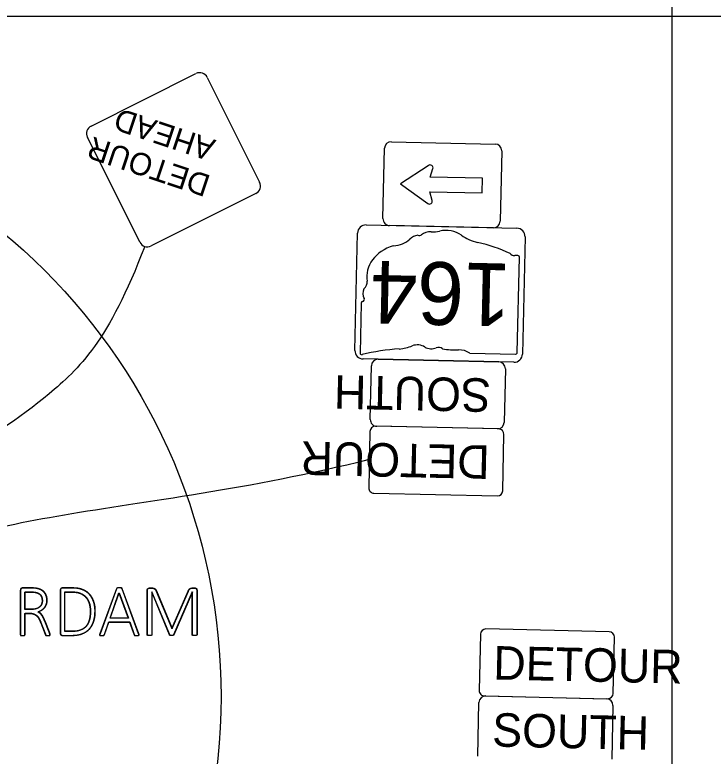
# Model space of a CAD drawing. Extents: x -202 to 1556, y 0 to 676.
# Drawn here: x 251.9 to 356.1, y 109.6 to 220.2 of the extents above; entities that cross this region are included whole.
import ezdxf

# ---------------------------------------------------------------- set-up
doc = ezdxf.new("R2010")
doc.units = 0
for name, color, linetype in [('GM_X_Minor_Lake', 7, 'Continuous'), ('GM_X_Minor_Lake_Text', 7, 'Continuous'), ('GM_X_Minor_River_Text', 7, 'Continuous'), ('GM_X_Unincorporated', 7, 'Continuous'), ('SH_Data', 7, 'Continuous')]:
    doc.layers.add(name, color=color, linetype=linetype)

msp = doc.modelspace()

# ---------------------------------------------------------------- linework, layer by layer
at = {"layer": 'GM_X_Minor_Lake'}
for p, q in [((326.89, 169.82), (327.2, 184.05)), ((303.61, 177.18), (303.45, 169.74)), ((303.61, 177.18), (303.61, 177.18)), ((319.79, 169.73), (326.65, 169.58)), ((306.14, 168.81), (324.14, 168.41)), ((304.95, 159.83), (305.12, 167.83)), ((325.12, 167.39), (324.94, 159.39)), ((323.92, 158.41), (305.92, 158.81)), ((322.19, 118.56), (340.18, 118.16)), ((320.99, 109.58), (321.17, 117.58)), ((341.16, 117.14), (340.99, 109.14))]:
    msp.add_line(p, q, dxfattribs=at)
for points in [[(263.29, 203.61), (278.94, 211.44)], [(280.62, 210.88), (288.44, 195.23)], [(270.55, 186.28), (262.73, 201.94)], [(287.88, 193.55), (272.23, 185.72)], [(304.33, 188.85), (326.83, 188.36)], [(302.67, 170.13), (303.06, 187.63)], [(328.05, 187.08), (327.67, 169.58)], [(326.39, 168.36), (303.89, 168.85)], [(324.12, 158.41), (305.72, 158.81)], [(304.91, 158.03), (304.72, 149.63)], [(324.72, 149.19), (324.9, 157.59)], [(305.5, 148.81), (323.9, 148.41)], [(340.6, 128.15), (322.21, 128.56)], [(321.39, 127.78), (321.21, 119.38)], [(341.2, 118.94), (341.39, 127.34)], [(321.99, 118.56), (340.38, 118.16)]]:
    msp.add_lwpolyline(points, dxfattribs=at)
for centre, radius, start, end in [((279.5, 210.32), 1.25, 26.565, 116.565), ((263.85, 202.49), 1.25, 116.565, 206.565), ((287.32, 194.67), 1.25, 296.565, 26.565), ((304.31, 187.6), 1.25, 88.742, 178.742), ((326.8, 187.11), 1.25, 358.742, 88.742), ((271.67, 186.84), 1.25, 206.565, 296.565), ((303.92, 170.1), 1.25, 178.742, 268.742), ((326.42, 169.61), 1.25, 268.742, 358.742), ((306.12, 167.81), 1, 88.742, 178.742), ((324.12, 167.41), 1, 358.742, 88.742), ((305.95, 159.81), 1, 178.742, 268.742), ((323.94, 159.41), 1, 268.742, 358.742), ((305.71, 158.01), 0.8, 88.742, 178.742), ((324.1, 157.61), 0.8, 358.742, 88.742), ((305.52, 149.61), 0.8, 178.742, 268.742), ((323.92, 149.21), 0.8, 268.742, 358.742), ((322.19, 127.76), 0.8, 88.742, 178.742), ((340.59, 127.35), 0.8, 358.742, 88.742), ((322.17, 117.56), 1, 88.742, 178.742), ((322.01, 119.36), 0.8, 178.742, 268.742), ((340.4, 118.96), 0.8, 268.742, 358.742), ((340.16, 117.16), 1, 358.742, 88.742)]:
    msp.add_arc(centre, radius, start, end, dxfattribs=at)
for centre, major_axis, start_param, end_param in [((316.25, 185.18), (-3.56, 0.08), 4.026481, 4.996735), ((312.45, 185.75), (-2.01, 0.04), 4.937069, 5.64225), ((312.26, 187.71), (-0.534, 0.012), 1.147584, 2.315152), ((313.95, 186.3), (-1.9, 0.04), 4.691044, 5.507374), ((314.29, 190.15), (-2.93, 0.06), 1.495662, 1.94098), ((322.44, 190.55), (-5.61, 0.12), 0.823519, 1.323587), ((308.19, 188.46), (-3.4, 0.07), 1.647645, 2.488434), ((316.69, 172.31), (-17.94, 0.39), 4.195997, 4.488961), ((310.65, 181.09), (-6.22, 0.14), 5.101752, 6.440018), ((326.48, 184.89), (-0.754, 0.017), 0.519207, 1.627899), ((326.86, 182.63), (-2.09, 0.05), 4.665946, 4.897461), ((326.93, 184.09), (-0.274, 0.006), 3.00124, 4.508301), ((302.74, 180.32), (-1.76, 0.04), 2.387724, 3.262537), ((306.27, 178.61), (-2.42, 0.05), 5.934695, 6.695948), ((303.89, 177.2), (-0.279, 0.006), 5.05454, 6.418171), ((303.68, 177.73), (-0.404, 0.009), 1.883978, 3.671073), ((308.73, 174.32), (-5, 0.11), 1.699011, 2.107814), ((311.97, 169.43), (-1.9, 0.04), 4.081561, 5.145723), ((314.06, 171.64), (-1.58, 0.03), 0.950623, 2.079405), ((315.14, 169.98), (-0.76, 0.017), 3.836095, 5.185415), ((303.7, 169.7), (-0.261, 0.006), 6.141152, 7.989035), ((311.37, 150.51), (-24.85, 0.55), 4.814394, 5.042369), ((317.46, 177.78), (-9.45, 0.21), 1.404758, 1.657858), ((318.12, 168.12), (-2.63, 0.06), 4.042523, 4.731795), ((326.62, 169.8), (-0.271, 0.006), 1.712693, 3.28349)]:
    msp.add_ellipse(centre, major_axis=major_axis, ratio=0.8, start_param=start_param, end_param=end_param, dxfattribs=at)
at = {"layer": 'GM_X_Minor_Lake_Text'}
for p, q in [((306.85, 189.79), (307.08, 200.29)), ((308.11, 201.27), (323.6, 200.93)), ((324.58, 199.91), (324.35, 189.41)), ((313.61, 197.69), (309.47, 194.99)), ((313.87, 195.99), (314.29, 197.26)), ((321.68, 195.81), (313.87, 195.99)), ((321.63, 193.63), (321.68, 195.81)), ((309.47, 194.99), (313.54, 192.05)), ((313.82, 193.8), (321.63, 193.63)), ((314.19, 192.51), (313.82, 193.8)), ((323.33, 188.43), (307.83, 188.77))]:
    msp.add_line(p, q, dxfattribs=at)
for centre, radius, start, end in [((308.08, 200.27), 1, 88.742, 178.742), ((323.58, 199.93), 1, 358.742, 88.742), ((313.9, 197.39), 0.417, 341.5374, 133.7516), ((313.79, 192.39), 0.417, 234.1532, 15.9466), ((307.85, 189.77), 1, 178.742, 268.742), ((323.35, 189.43), 1, 268.742, 358.742)]:
    msp.add_arc(centre, radius, start, end, dxfattribs=at)
at = {"layer": 'GM_X_Minor_River_Text'}
for p, q in [((350, 10), (350, 430)), ((30, 220), (640, 220))]:
    msp.add_line(p, q, dxfattribs=at)
at = {"layer": 'GM_X_Unincorporated'}
for p, q in [((252.72, 134.32), (252.72, 127.71)), ((252.76, 134.34), (252.76, 127.72)), ((254.35, 134.67), (253.02, 134.67)), ((254.39, 134.68), (253.06, 134.68)), ((258.67, 134.32), (258.67, 127.94)), ((258.71, 134.34), (258.71, 127.96)), ((260.46, 134.67), (258.98, 134.67)), ((260.5, 134.68), (259.02, 134.68)), ((267.05, 134.55), (264.58, 127.82)), ((267.09, 134.56), (264.62, 127.84)), ((270.38, 127.82), (267.9, 134.55)), ((270.42, 127.84), (267.94, 134.56)), ((271.66, 127.71), (271.66, 134.32)), ((271.7, 127.72), (271.7, 134.34)), ((271.97, 134.67), (272.33, 134.67)), ((272.01, 134.68), (272.37, 134.68)), ((278.35, 134.67), (278.75, 134.67)), ((278.39, 134.68), (278.78, 134.68)), ((279.05, 134.32), (279.05, 127.71)), ((279.09, 134.34), (279.09, 127.72)), ((255.97, 132.77), (255.97, 132.77)), ((256.01, 132.79), (256.01, 132.79)), ((263.15, 131.2), (263.15, 131.2)), ((263.19, 131.22), (263.19, 131.22)), ((263.87, 131.24), (263.87, 131.24)), ((263.91, 131.25), (263.91, 131.25)), ((255.76, 129.49), (256.42, 127.78)), ((255.8, 129.51), (256.46, 127.79)), ((257.03, 128.08), (256.37, 129.73)), ((257.07, 128.1), (256.41, 129.75)), ((257.14, 127.72), (257.14, 127.72)), ((257.18, 127.73), (257.18, 127.73)), ((258.98, 127.6), (260.37, 127.6)), ((259.02, 127.61), (260.41, 127.61))]:
    msp.add_line(p, q, dxfattribs=at)
for points in [[(254.4, 131.48), (253.38, 131.48), (253.38, 134.07), (254.26, 134.07)], [(254.44, 131.5), (253.42, 131.5), (253.42, 134.09), (254.3, 134.09)], [(260.43, 128.19), (259.34, 128.19), (259.34, 134.07), (260.43, 134.07)], [(260.47, 128.21), (259.38, 128.21), (259.38, 134.09), (260.47, 134.09)], [(274.98, 127.67), (272.33, 134.08), (272.33, 134.08), (272.33, 127.71)], [(275.02, 127.69), (272.37, 134.1), (272.37, 134.1), (272.37, 127.72)], [(272.98, 134.22), (275.32, 128.61), (275.35, 128.61), (277.78, 134.2)], [(273.02, 134.24), (275.36, 128.62), (275.39, 128.62), (277.82, 134.22)], [(278.38, 127.71), (278.38, 134.08), (278.37, 134.08), (275.59, 127.67)], [(278.42, 127.72), (278.42, 134.1), (278.41, 134.1), (275.63, 127.69)], [(253.38, 127.71), (253.38, 130.89), (254.12, 130.89)], [(253.42, 127.72), (253.42, 130.91), (254.16, 130.91)], [(265.26, 127.72), (265.91, 129.59), (269.01, 129.59), (269.69, 127.71)], [(265.3, 127.73), (265.95, 129.61), (269.05, 129.61), (269.73, 127.72)]]:
    msp.add_lwpolyline(points, dxfattribs=at)
for points in [[(267.44, 133.95), (268.81, 130.15), (266.11, 130.15), (267.44, 133.95)], [(267.48, 133.97), (268.85, 130.17), (266.15, 130.17), (267.48, 133.97)]]:
    msp.add_lwpolyline(points, close=True, dxfattribs=at)
for points in [[(252.82, 134.59), (252.72, 134.52), (252.72, 134.32)], [(252.86, 134.61), (252.76, 134.54), (252.76, 134.34)], [(253.02, 134.67), (252.92, 134.67), (252.82, 134.59)], [(253.06, 134.68), (252.96, 134.68), (252.86, 134.61)], [(254.26, 134.07), (254.56, 134.07), (254.74, 134.05)], [(254.3, 134.09), (254.6, 134.09), (254.78, 134.07)], [(254.79, 134.65), (254.61, 134.67), (254.35, 134.67)], [(254.83, 134.67), (254.65, 134.68), (254.39, 134.68)], [(254.74, 134.05), (254.93, 134.04), (255.09, 133.99)], [(254.78, 134.07), (254.97, 134.05), (255.13, 134.01)], [(255.1, 134.62), (254.96, 134.64), (254.79, 134.65)], [(255.14, 134.63), (255, 134.66), (254.83, 134.67)], [(255.09, 133.99), (255.57, 133.86), (255.77, 133.54)], [(255.8, 134.39), (255.5, 134.55), (255.1, 134.62)], [(255.13, 134.01), (255.61, 133.87), (255.81, 133.56)], [(255.84, 134.41), (255.54, 134.56), (255.14, 134.63)], [(256.3, 134), (256.11, 134.23), (255.8, 134.39)], [(256.34, 134.01), (256.15, 134.25), (255.84, 134.41)], [(256.59, 133.47), (256.5, 133.77), (256.3, 134)], [(256.63, 133.49), (256.54, 133.78), (256.34, 134.01)], [(258.78, 134.59), (258.67, 134.52), (258.67, 134.32)], [(258.81, 134.61), (258.71, 134.54), (258.71, 134.34)], [(258.98, 134.67), (258.88, 134.67), (258.78, 134.59)], [(259.02, 134.68), (258.92, 134.68), (258.81, 134.61)], [(260.43, 134.07), (261.2, 134.07), (261.69, 133.86)], [(261.98, 134.42), (261.36, 134.67), (260.46, 134.67)], [(260.47, 134.09), (261.24, 134.09), (261.73, 133.87)], [(262.02, 134.44), (261.4, 134.68), (260.5, 134.68)], [(261.73, 133.87), (262.23, 133.66), (262.56, 133.28)], [(263.02, 133.73), (262.6, 134.18), (261.98, 134.42)], [(263.06, 133.74), (262.64, 134.19), (262.02, 134.44)], [(267.1, 134.62), (267.07, 134.59), (267.05, 134.55)], [(267.14, 134.64), (267.11, 134.61), (267.09, 134.56)], [(267.18, 134.67), (267.13, 134.65), (267.1, 134.62)], [(267.22, 134.68), (267.17, 134.67), (267.14, 134.64)], [(267.31, 134.69), (267.24, 134.68), (267.18, 134.67)], [(267.35, 134.71), (267.27, 134.7), (267.22, 134.68)], [(267.48, 134.7), (267.38, 134.7), (267.31, 134.69)], [(267.52, 134.72), (267.42, 134.72), (267.35, 134.71)], [(267.65, 134.69), (267.57, 134.7), (267.48, 134.7)], [(267.69, 134.71), (267.61, 134.72), (267.52, 134.72)], [(267.77, 134.67), (267.72, 134.68), (267.65, 134.69)], [(267.81, 134.68), (267.76, 134.7), (267.69, 134.71)], [(267.86, 134.62), (267.83, 134.65), (267.77, 134.67)], [(267.9, 134.64), (267.87, 134.67), (267.81, 134.68)], [(267.9, 134.55), (267.89, 134.59), (267.86, 134.62)], [(267.94, 134.56), (267.93, 134.61), (267.9, 134.64)], [(271.66, 134.32), (271.66, 134.52), (271.77, 134.59)], [(271.7, 134.34), (271.7, 134.54), (271.81, 134.61)], [(271.77, 134.59), (271.87, 134.67), (271.97, 134.67)], [(271.81, 134.61), (271.91, 134.68), (272.01, 134.68)], [(272.33, 134.67), (272.47, 134.67), (272.57, 134.64)], [(272.37, 134.68), (272.51, 134.68), (272.61, 134.65)], [(272.57, 134.64), (272.67, 134.61), (272.75, 134.55)], [(272.61, 134.65), (272.71, 134.62), (272.79, 134.57)], [(272.75, 134.55), (272.83, 134.49), (272.89, 134.41)], [(272.79, 134.57), (272.87, 134.51), (272.93, 134.43)], [(272.89, 134.41), (272.94, 134.33), (272.98, 134.22)], [(272.93, 134.43), (272.98, 134.34), (273.02, 134.24)], [(277.78, 134.2), (277.83, 134.33), (277.9, 134.42)], [(277.82, 134.22), (277.87, 134.35), (277.93, 134.44)], [(277.9, 134.42), (277.96, 134.51), (278.03, 134.57)], [(277.93, 134.44), (278, 134.53), (278.07, 134.59)], [(278.03, 134.57), (278.09, 134.62), (278.17, 134.65)], [(278.07, 134.59), (278.13, 134.64), (278.21, 134.66)], [(278.17, 134.65), (278.25, 134.67), (278.35, 134.67)], [(278.21, 134.66), (278.29, 134.68), (278.39, 134.68)], [(278.75, 134.67), (278.79, 134.67), (278.85, 134.65)], [(278.78, 134.68), (278.83, 134.68), (278.89, 134.67)], [(278.85, 134.65), (278.9, 134.63), (278.95, 134.59)], [(278.89, 134.67), (278.94, 134.65), (278.99, 134.61)], [(278.95, 134.59), (278.99, 134.55), (279.02, 134.49)], [(278.99, 134.61), (279.03, 134.57), (279.06, 134.5)], [(279.02, 134.49), (279.05, 134.42), (279.05, 134.32)], [(279.06, 134.5), (279.09, 134.44), (279.09, 134.34)], [(255.77, 133.54), (255.97, 133.23), (255.97, 132.77)], [(255.81, 133.56), (256.01, 133.24), (256.01, 132.79)], [(255.97, 132.77), (255.97, 132.5), (255.88, 132.27)], [(256.01, 132.79), (256.01, 132.52), (255.92, 132.28)], [(256.69, 132.84), (256.69, 133.18), (256.59, 133.47)], [(256.59, 132.22), (256.69, 132.49), (256.69, 132.84)], [(256.73, 132.86), (256.73, 133.2), (256.63, 133.49)], [(256.63, 132.23), (256.73, 132.51), (256.73, 132.86)], [(261.69, 133.86), (262.19, 133.64), (262.52, 133.26)], [(262.52, 133.26), (262.84, 132.88), (263, 132.35)], [(262.56, 133.28), (262.88, 132.89), (263.04, 132.37)], [(263.65, 132.64), (263.44, 133.27), (263.02, 133.73)], [(263.69, 132.66), (263.48, 133.29), (263.06, 133.74)], [(255.6, 131.86), (255.4, 131.68), (255.11, 131.58)], [(255.64, 131.87), (255.44, 131.7), (255.15, 131.6)], [(255.88, 132.27), (255.79, 132.03), (255.6, 131.86)], [(255.92, 132.28), (255.83, 132.05), (255.64, 131.87)], [(255.88, 131.37), (256.13, 131.52), (256.31, 131.73)], [(255.92, 131.39), (256.17, 131.54), (256.35, 131.75)], [(256.31, 131.73), (256.49, 131.94), (256.59, 132.22)], [(256.35, 131.75), (256.53, 131.96), (256.63, 132.23)], [(263, 132.35), (263.15, 131.82), (263.15, 131.2)], [(263.04, 132.37), (263.19, 131.84), (263.19, 131.22)], [(263.87, 131.24), (263.87, 132.01), (263.65, 132.64)], [(263.91, 131.25), (263.91, 132.03), (263.69, 132.66)], [(254.12, 130.89), (254.48, 130.89), (254.74, 130.78)], [(254.16, 130.91), (254.52, 130.91), (254.78, 130.8)], [(255.11, 131.58), (254.81, 131.48), (254.4, 131.48)], [(255.15, 131.6), (254.85, 131.5), (254.44, 131.5)], [(254.74, 130.78), (255.01, 130.67), (255.19, 130.49)], [(254.78, 130.8), (255.05, 130.69), (255.23, 130.5)], [(255.33, 131.11), (255.63, 131.22), (255.88, 131.37)], [(255.65, 130.91), (255.51, 131.03), (255.33, 131.11)], [(255.37, 131.13), (255.67, 131.23), (255.92, 131.39)], [(255.69, 130.93), (255.55, 131.05), (255.37, 131.13)], [(255.92, 130.62), (255.8, 130.79), (255.65, 130.91)], [(255.96, 130.64), (255.84, 130.81), (255.69, 130.93)], [(256.15, 130.23), (256.05, 130.45), (255.92, 130.62)], [(256.19, 130.25), (256.09, 130.47), (255.96, 130.64)], [(263.15, 131.2), (263.15, 130.42), (262.99, 129.86)], [(263.19, 131.22), (263.19, 130.44), (263.03, 129.87)], [(263.64, 129.67), (263.87, 130.35), (263.87, 131.24)], [(263.68, 129.68), (263.91, 130.36), (263.91, 131.25)], [(255.19, 130.49), (255.38, 130.3), (255.51, 130.04)], [(255.23, 130.5), (255.42, 130.31), (255.55, 130.06)], [(255.51, 130.04), (255.64, 129.78), (255.76, 129.49)], [(255.55, 130.06), (255.68, 129.8), (255.8, 129.51)], [(256.37, 129.73), (256.26, 130.01), (256.15, 130.23)], [(256.41, 129.75), (256.3, 130.02), (256.19, 130.25)], [(262.99, 129.86), (262.82, 129.29), (262.49, 128.92)], [(263.03, 129.87), (262.86, 129.31), (262.53, 128.94)], [(262.98, 128.53), (263.42, 128.99), (263.64, 129.67)], [(263.02, 128.54), (263.46, 129), (263.68, 129.68)], [(261.65, 128.37), (261.15, 128.19), (260.43, 128.19)], [(261.69, 128.39), (261.19, 128.21), (260.47, 128.21)], [(262.49, 128.92), (262.15, 128.55), (261.65, 128.37)], [(262.53, 128.94), (262.19, 128.56), (261.69, 128.39)], [(261.9, 127.83), (262.54, 128.07), (262.98, 128.53)], [(261.94, 127.85), (262.58, 128.08), (263.02, 128.54)], [(252.72, 127.71), (252.72, 127.67), (252.73, 127.65)], [(252.73, 127.65), (252.75, 127.62), (252.79, 127.6)], [(252.76, 127.72), (252.76, 127.69), (252.77, 127.66)], [(252.77, 127.66), (252.79, 127.64), (252.83, 127.62)], [(252.79, 127.6), (252.83, 127.59), (252.89, 127.58)], [(252.83, 127.62), (252.87, 127.6), (252.93, 127.59)], [(252.89, 127.58), (252.96, 127.57), (253.05, 127.57)], [(252.93, 127.59), (253, 127.58), (253.09, 127.58)], [(253.05, 127.57), (253.15, 127.57), (253.21, 127.58)], [(253.09, 127.58), (253.19, 127.58), (253.25, 127.59)], [(253.21, 127.58), (253.27, 127.59), (253.31, 127.6)], [(253.25, 127.59), (253.31, 127.6), (253.35, 127.62)], [(253.31, 127.6), (253.35, 127.62), (253.37, 127.65)], [(253.35, 127.62), (253.39, 127.64), (253.41, 127.66)], [(253.37, 127.65), (253.38, 127.67), (253.38, 127.71)], [(253.41, 127.66), (253.42, 127.69), (253.42, 127.72)], [(256.42, 127.78), (256.44, 127.71), (256.47, 127.67)], [(256.46, 127.79), (256.48, 127.73), (256.51, 127.69)], [(256.47, 127.67), (256.49, 127.63), (256.54, 127.61)], [(256.51, 127.69), (256.53, 127.65), (256.58, 127.62)], [(256.54, 127.61), (256.58, 127.58), (256.64, 127.57)], [(256.58, 127.62), (256.62, 127.6), (256.68, 127.59)], [(256.64, 127.57), (256.71, 127.57), (256.8, 127.57)], [(256.68, 127.59), (256.75, 127.58), (256.84, 127.58)], [(256.8, 127.57), (256.9, 127.57), (256.97, 127.58)], [(256.84, 127.58), (256.94, 127.58), (257.01, 127.59)], [(256.97, 127.58), (257.04, 127.59), (257.08, 127.61)], [(257.01, 127.59), (257.08, 127.6), (257.12, 127.62)], [(257.12, 127.82), (257.11, 127.89), (257.03, 128.08)], [(257.16, 127.84), (257.15, 127.91), (257.07, 128.1)], [(257.08, 127.61), (257.12, 127.63), (257.13, 127.65)], [(257.14, 127.72), (257.14, 127.75), (257.12, 127.82)], [(257.12, 127.62), (257.16, 127.64), (257.17, 127.67)], [(257.13, 127.65), (257.14, 127.68), (257.14, 127.72)], [(257.18, 127.73), (257.18, 127.77), (257.16, 127.84)], [(257.17, 127.67), (257.18, 127.7), (257.18, 127.73)], [(258.67, 127.94), (258.67, 127.75), (258.78, 127.67)], [(258.71, 127.96), (258.71, 127.76), (258.81, 127.69)], [(258.78, 127.67), (258.88, 127.6), (258.98, 127.6)], [(258.81, 127.69), (258.92, 127.61), (259.02, 127.61)], [(260.37, 127.6), (261.26, 127.6), (261.9, 127.83)], [(260.41, 127.61), (261.3, 127.61), (261.94, 127.85)], [(264.58, 127.82), (264.54, 127.74), (264.55, 127.69)], [(264.55, 127.69), (264.55, 127.64), (264.59, 127.61)], [(264.62, 127.84), (264.58, 127.76), (264.59, 127.71)], [(264.59, 127.71), (264.59, 127.66), (264.62, 127.63)], [(264.59, 127.61), (264.62, 127.59), (264.7, 127.58)], [(264.62, 127.63), (264.66, 127.6), (264.74, 127.59)], [(264.7, 127.58), (264.77, 127.57), (264.89, 127.57)], [(264.74, 127.59), (264.81, 127.58), (264.93, 127.58)], [(264.89, 127.57), (264.99, 127.57), (265.06, 127.58)], [(264.93, 127.58), (265.03, 127.58), (265.1, 127.59)], [(265.06, 127.58), (265.13, 127.59), (265.17, 127.61)], [(265.1, 127.59), (265.17, 127.6), (265.21, 127.62)], [(265.17, 127.61), (265.2, 127.63), (265.23, 127.65)], [(265.21, 127.62), (265.24, 127.64), (265.26, 127.67)], [(265.23, 127.65), (265.25, 127.68), (265.26, 127.72)], [(265.26, 127.67), (265.29, 127.7), (265.3, 127.73)], [(269.69, 127.71), (269.71, 127.67), (269.73, 127.64)], [(269.73, 127.72), (269.75, 127.69), (269.77, 127.66)], [(269.73, 127.64), (269.74, 127.61), (269.78, 127.6)], [(269.77, 127.66), (269.78, 127.63), (269.82, 127.61)], [(269.78, 127.6), (269.82, 127.58), (269.89, 127.57)], [(269.82, 127.61), (269.86, 127.6), (269.93, 127.59)], [(269.89, 127.57), (269.96, 127.57), (270.07, 127.57)], [(269.93, 127.59), (270, 127.58), (270.11, 127.58)], [(270.07, 127.57), (270.19, 127.57), (270.26, 127.57)], [(270.11, 127.58), (270.23, 127.58), (270.3, 127.59)], [(270.26, 127.57), (270.33, 127.58), (270.37, 127.61)], [(270.3, 127.59), (270.37, 127.6), (270.41, 127.63)], [(270.37, 127.61), (270.4, 127.64), (270.41, 127.69)], [(270.41, 127.69), (270.41, 127.74), (270.38, 127.82)], [(270.41, 127.63), (270.44, 127.65), (270.45, 127.7)], [(270.45, 127.7), (270.45, 127.76), (270.42, 127.84)], [(271.68, 127.65), (271.66, 127.67), (271.66, 127.71)], [(271.73, 127.6), (271.69, 127.62), (271.68, 127.65)], [(271.72, 127.66), (271.7, 127.69), (271.7, 127.72)], [(271.77, 127.62), (271.73, 127.64), (271.72, 127.66)], [(271.83, 127.58), (271.77, 127.59), (271.73, 127.6)], [(271.87, 127.59), (271.81, 127.6), (271.77, 127.62)], [(271.98, 127.57), (271.89, 127.57), (271.83, 127.58)], [(272.02, 127.58), (271.93, 127.58), (271.87, 127.59)], [(272.15, 127.58), (272.09, 127.57), (271.98, 127.57)], [(272.19, 127.59), (272.13, 127.58), (272.02, 127.58)], [(272.26, 127.6), (272.21, 127.59), (272.15, 127.58)], [(272.29, 127.62), (272.25, 127.6), (272.19, 127.59)], [(272.31, 127.65), (272.3, 127.62), (272.26, 127.6)], [(272.35, 127.66), (272.34, 127.64), (272.29, 127.62)], [(272.33, 127.71), (272.33, 127.67), (272.31, 127.65)], [(272.37, 127.72), (272.37, 127.69), (272.35, 127.66)], [(275.01, 127.63), (274.99, 127.65), (274.98, 127.67)], [(275.07, 127.6), (275.03, 127.61), (275.01, 127.63)], [(275.05, 127.64), (275.03, 127.66), (275.02, 127.69)], [(275.11, 127.61), (275.07, 127.63), (275.05, 127.64)], [(275.16, 127.57), (275.1, 127.58), (275.07, 127.6)], [(275.2, 127.59), (275.14, 127.6), (275.11, 127.61)], [(275.29, 127.57), (275.21, 127.57), (275.16, 127.57)], [(275.33, 127.58), (275.25, 127.58), (275.2, 127.59)], [(275.41, 127.57), (275.36, 127.57), (275.29, 127.57)], [(275.45, 127.59), (275.4, 127.58), (275.33, 127.58)], [(275.5, 127.6), (275.46, 127.58), (275.41, 127.57)], [(275.54, 127.61), (275.5, 127.6), (275.45, 127.59)], [(275.56, 127.63), (275.54, 127.61), (275.5, 127.6)], [(275.6, 127.64), (275.58, 127.63), (275.54, 127.61)], [(275.59, 127.67), (275.58, 127.65), (275.56, 127.63)], [(275.63, 127.69), (275.62, 127.66), (275.6, 127.64)], [(278.4, 127.65), (278.38, 127.67), (278.38, 127.71)], [(278.46, 127.6), (278.42, 127.62), (278.4, 127.65)], [(278.44, 127.66), (278.42, 127.69), (278.42, 127.72)], [(278.5, 127.62), (278.46, 127.64), (278.44, 127.66)], [(278.56, 127.58), (278.49, 127.59), (278.46, 127.6)], [(278.6, 127.59), (278.53, 127.6), (278.5, 127.62)], [(278.71, 127.57), (278.62, 127.57), (278.56, 127.58)], [(278.75, 127.58), (278.66, 127.58), (278.6, 127.59)], [(278.87, 127.58), (278.81, 127.57), (278.71, 127.57)], [(278.91, 127.59), (278.85, 127.58), (278.75, 127.58)], [(278.98, 127.6), (278.94, 127.59), (278.87, 127.58)], [(279.02, 127.62), (278.98, 127.6), (278.91, 127.59)], [(279.03, 127.65), (279.02, 127.62), (278.98, 127.6)], [(279.07, 127.66), (279.06, 127.64), (279.02, 127.62)], [(279.05, 127.71), (279.05, 127.67), (279.03, 127.65)], [(279.09, 127.72), (279.09, 127.69), (279.07, 127.66)]]:
    msp.add_open_spline(points, degree=2, dxfattribs=at)
at = {"layer": 'SH_Data'}
msp.add_circle((192.68, 118.45), 90, dxfattribs=at)
for points in [[(271.28, 185.66), (265.89, 171.48), (256.99, 163.2), (243.71, 153.51), (211.73, 140.55), (193.98, 140.09)], [(304.81, 153.83), (286.64, 149.33), (255.81, 145.84), (230.47, 138.89), (205.7, 130.17), (189.94, 121.36)], [(318.25, 98.64), (296.15, 103.63), (275.17, 107.57), (247.73, 107.51), (203.85, 110.62), (195.4, 115.77)]]:
    msp.add_open_spline(points, degree=3, dxfattribs=at)

# ---------------------------------------------------------------- texts
at = {"layer": 'GM_X_Minor_Lake'}
for s, height, rotation, p in [('AHEAD', 3.333, 161.565, (282.03, 201.48)), ('DETOUR', 3.333, 161.565, (281.31, 196.16)), ('164', 9.375, 178.742, (326.03, 183.07)), ('SOUTH', 5, 178.742, (323, 165.93)), ('DETOUR', 5, 178.742, (322.83, 155.94)), ('DETOUR', 5, 358.742, (323.28, 121.03)), ('SOUTH', 5, 358.742, (323.11, 111.03))]:
    msp.add_text(s, height=height, rotation=rotation, dxfattribs=at).set_placement(p)

doc.saveas('drawing.dxf')
